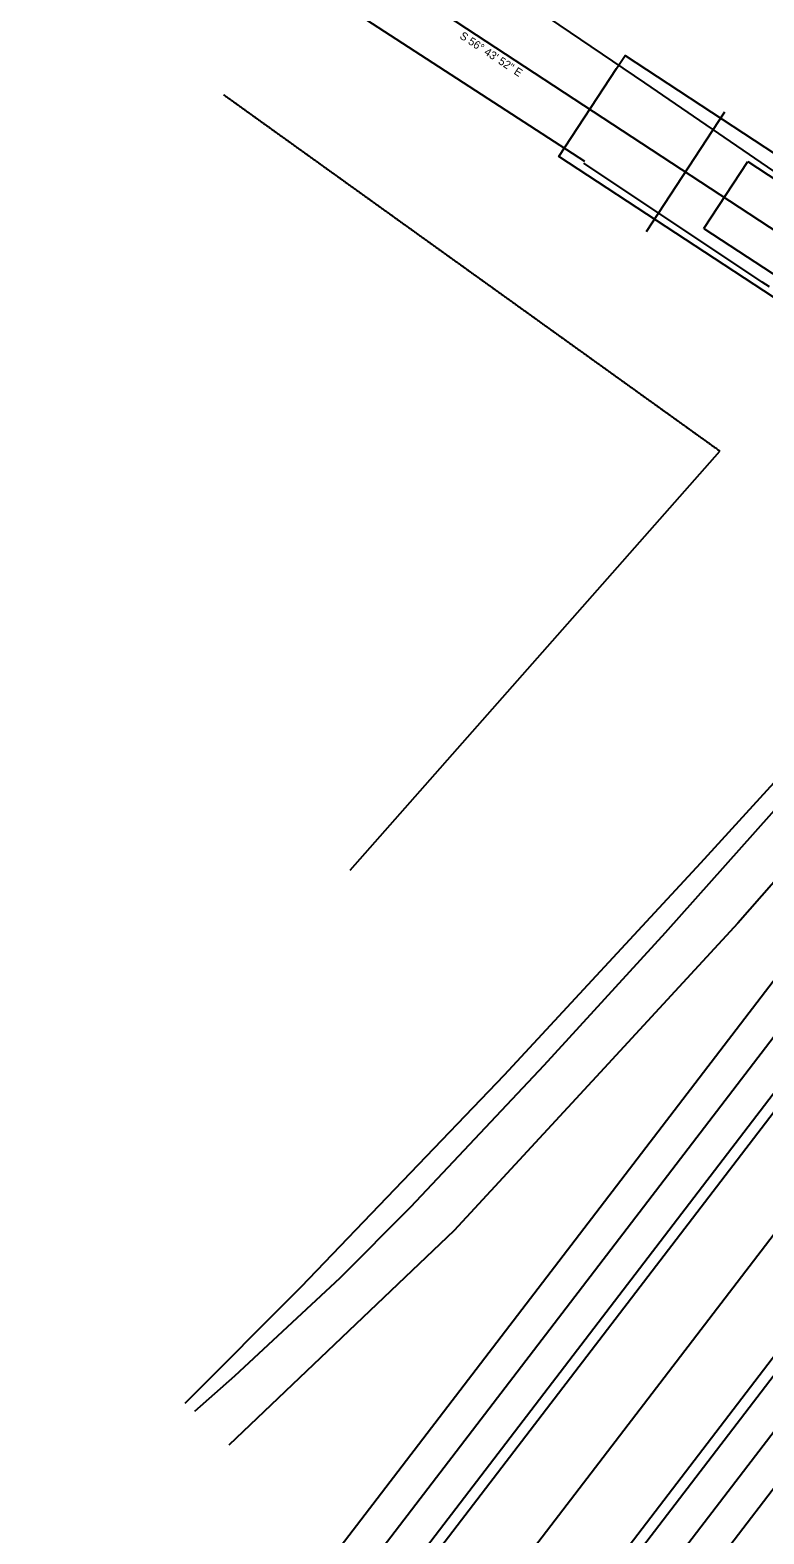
# Model space of a CAD drawing. Extents: x 1811884 to 1864767, y 229883 to 701064.
# Drawn here: x 1857252 to 1857509, y 693923 to 694449 of the extents above; entities that cross this region are included whole.
import ezdxf

# ---------------------------------------------------------------- set-up
doc = ezdxf.new("R2010")
doc.units = 0
for name, color, linetype in [('GE_X_CL_20', 7, 'Continuous'), ('GK_Patterns', 7, 'Continuous'), ('PM_X_Dotted_Line', 7, 'Continuous'), ('PV_P_EOP', 7, 'Continuous'), ('PV_X_EOP', 7, 'Continuous'), ('PV_X_Shoulder', 7, 'Continuous'), ('RD_P_GR_Lt', 7, 'Continuous'), ('RD_P_GR_Rt', 7, 'Continuous'), ('RD_X_GR_Lt', 7, 'Continuous'), ('RD_X_GR_Rt', 7, 'Continuous'), ('RW_P_Const_Limits', 7, 'Continuous'), ('RW_X_Esmt_LA', 7, 'Continuous'), ('RW_X_Fee_RW', 7, 'Continuous'), ('SC_Scratch1', 7, 'Continuous')]:
    doc.layers.add(name, color=color, linetype=linetype)

msp = doc.modelspace()

# ---------------------------------------------------------------- linework, layer by layer
at = {"layer": 'GE_X_CL_20'}
for p, q in [((1856038.27, 695346.31), (1858797.33, 693536.09)), ((1849938.53, 684134.24), (1857781.86, 694380.23))]:
    msp.add_line(p, q, dxfattribs=at)
at = {"layer": 'GK_Patterns'}
msp.add_line((1857495, 694420.44), (1857467.58, 694378.64), dxfattribs=at)
at = {"layer": 'PM_X_Dotted_Line'}
for p, q in [((1849895.65, 684167.07), (1857634.93, 694277.14)), ((1849905.18, 684159.77), (1857644.6, 694270.02)), ((1849971.88, 684108.72), (1857715.1, 694223.93))]:
    msp.add_line(p, q, dxfattribs=at)
msp.add_lwpolyline([(1857597.14, 694247.78), (1857499.66, 694136.79), (1857452.86, 694086.05), (1857400.42, 694029.19), (1857321.55, 693954.09)], dxfattribs=at)
at = {"layer": 'PV_P_EOP'}
for p, q in [((1857487.73, 694379.77), (1857503.09, 694403.18)), ((1857503.09, 694403.18), (1857550.9, 694371.81)), ((1857487.73, 694379.77), (1857533.83, 694349.52))]:
    msp.add_line(p, q, dxfattribs=at)
at = {"layer": 'PV_X_EOP'}
for p, q in [((1849917.89, 684150.05), (1857657.99, 694261.19)), ((1849959.18, 684118.44), (1857701.58, 694232.59))]:
    msp.add_line(p, q, dxfattribs=at)
msp.add_lwpolyline([(1857606.72, 694294.54), (1857568.77, 694249.34), (1857528.08, 694203.18), (1857486.54, 694157.74), (1857417.89, 694083.55), (1857346.7, 694009.38), (1857306.23, 693968.66)], dxfattribs=at)
at = {"layer": 'PV_X_Shoulder'}
for p, q in [((1849914.71, 684152.48), (1857654.31, 694262.96)), ((1849962.35, 684116.01), (1857705.14, 694230.65)), ((1849981.41, 684101.42), (1857725.06, 694217.19))]:
    msp.add_line(p, q, dxfattribs=at)
msp.add_lwpolyline([(1857611.94, 694290.62), (1857587.74, 694262.22), (1857555.83, 694224.77), (1857516.23, 694180.44), (1857474.18, 694133.37), (1857431.78, 694086.9), (1857385.17, 694037.4), (1857360.36, 694012.59), (1857323.57, 693978.21), (1857309.55, 693965.85)], dxfattribs=at)
at = {"layer": 'RD_P_GR_Lt'}
msp.add_line((1857508.16, 694361.03), (1857445.75, 694402.62), dxfattribs=at)
at = {"layer": 'RD_P_GR_Rt'}
msp.add_line((1857528.96, 694388.35), (1857467.05, 694430.68), dxfattribs=at)
at = {"layer": 'RD_X_GR_Lt'}
msp.add_line((1857446.11, 694403.17), (1857367.47, 694454.21), dxfattribs=at)
at = {"layer": 'RD_X_GR_Rt'}
msp.add_line((1857467.05, 694430.68), (1857374.01, 694493.93), dxfattribs=at)
at = {"layer": 'RW_P_Const_Limits'}
msp.add_lwpolyline([(1857457.17, 694435.7), (1857460.19, 694440.29), (1857550.46, 694381.06), (1857566.92, 694374.74), (1857583.72, 694363.9), (1857585.98, 694354.91), (1857812.54, 694207.41), (1857831.82, 694200.62), (1857860.09, 694181.63), (1857883.95, 694161.73), (1857938.72, 694129.31), (1857939.81, 694128.59), (1857935.42, 694121.92), (1857912.81, 694087.45), (1857834.01, 694143.46), (1857818.03, 694145.83), (1857799.92, 694157.36), (1857791.32, 694171.29), (1857565.48, 694319.69), (1857549.3, 694322.83), (1857529.11, 694336.08), (1857518.94, 694351.25), (1857437.03, 694404.99)], close=True, dxfattribs=at)
at = {"layer": 'RW_X_Esmt_LA'}
msp.add_line((1857364.06, 694155.25), (1857493.37, 694301.92), dxfattribs=at)
at = {"layer": 'RW_X_Fee_RW'}
for points in [[(1857319.67, 694426.64), (1857320.45, 694426.08), (1857321.23, 694425.52), (1857322.02, 694424.96), (1857322.8, 694424.4), (1857323.58, 694423.84), (1857324.36, 694423.27), (1857325.15, 694422.71), (1857325.93, 694422.15), (1857326.71, 694421.59), (1857327.49, 694421.03), (1857328.28, 694420.46), (1857329.06, 694419.9), (1857329.84, 694419.34), (1857330.62, 694418.78), (1857331.41, 694418.22), (1857332.19, 694417.65), (1857332.97, 694417.09), (1857333.75, 694416.53), (1857334.53, 694415.97), (1857335.32, 694415.41), (1857336.1, 694414.85), (1857336.88, 694414.28), (1857337.66, 694413.72), (1857338.45, 694413.16), (1857339.23, 694412.6), (1857340.01, 694412.04), (1857340.79, 694411.47), (1857341.58, 694410.91), (1857342.36, 694410.35), (1857343.14, 694409.79), (1857343.92, 694409.23), (1857344.71, 694408.67), (1857345.49, 694408.1), (1857346.27, 694407.54), (1857347.05, 694406.98), (1857347.84, 694406.42), (1857348.62, 694405.86), (1857349.4, 694405.29), (1857350.18, 694404.73), (1857350.97, 694404.17), (1857351.75, 694403.61), (1857352.53, 694403.05), (1857353.31, 694402.49), (1857354.1, 694401.92), (1857354.88, 694401.36), (1857355.66, 694400.8), (1857356.44, 694400.24), (1857357.23, 694399.68), (1857358.01, 694399.11), (1857358.79, 694398.55), (1857359.57, 694397.99), (1857360.35, 694397.43), (1857361.14, 694396.87), (1857361.92, 694396.31), (1857362.7, 694395.74), (1857363.48, 694395.18), (1857364.27, 694394.62), (1857365.05, 694394.06), (1857365.83, 694393.5), (1857366.61, 694392.93), (1857367.4, 694392.37), (1857368.18, 694391.81), (1857368.96, 694391.25), (1857369.74, 694390.69), (1857370.53, 694390.13), (1857371.31, 694389.56), (1857372.09, 694389), (1857372.87, 694388.44), (1857373.66, 694387.88), (1857374.44, 694387.32), (1857375.22, 694386.75), (1857376, 694386.19), (1857376.79, 694385.63), (1857377.57, 694385.07)], [(1857377.57, 694385.07), (1857378.35, 694384.51), (1857379.13, 694383.94), (1857379.92, 694383.38), (1857380.7, 694382.82), (1857381.48, 694382.26), (1857382.26, 694381.7), (1857383.04, 694381.14), (1857383.83, 694380.57), (1857384.61, 694380.01), (1857385.39, 694379.45), (1857386.17, 694378.89), (1857386.96, 694378.33), (1857387.74, 694377.76), (1857388.52, 694377.2), (1857389.3, 694376.64), (1857390.09, 694376.08), (1857390.87, 694375.52), (1857391.65, 694374.96), (1857392.43, 694374.39), (1857393.22, 694373.83), (1857394, 694373.27), (1857394.78, 694372.71), (1857395.56, 694372.15), (1857396.35, 694371.58), (1857397.13, 694371.02), (1857397.91, 694370.46), (1857398.69, 694369.9), (1857399.48, 694369.34), (1857400.26, 694368.78), (1857401.04, 694368.21), (1857401.82, 694367.65), (1857402.61, 694367.09), (1857403.39, 694366.53), (1857404.17, 694365.97), (1857404.95, 694365.4), (1857405.73, 694364.84), (1857406.52, 694364.28), (1857407.3, 694363.72), (1857408.08, 694363.16), (1857408.86, 694362.6), (1857409.65, 694362.03), (1857410.43, 694361.47), (1857411.21, 694360.91), (1857411.99, 694360.35), (1857412.78, 694359.79), (1857413.56, 694359.22), (1857414.34, 694358.66), (1857415.12, 694358.1), (1857415.91, 694357.54), (1857416.69, 694356.98), (1857417.47, 694356.41), (1857418.25, 694355.85), (1857419.04, 694355.29), (1857419.82, 694354.73), (1857420.6, 694354.17), (1857421.38, 694353.61), (1857422.17, 694353.04), (1857422.95, 694352.48), (1857423.73, 694351.92), (1857424.51, 694351.36), (1857425.3, 694350.8), (1857426.08, 694350.23), (1857426.86, 694349.67), (1857427.64, 694349.11), (1857428.42, 694348.55), (1857429.21, 694347.99), (1857429.99, 694347.43), (1857430.77, 694346.86), (1857431.55, 694346.3), (1857432.34, 694345.74), (1857433.12, 694345.18), (1857433.9, 694344.62), (1857434.68, 694344.05), (1857435.47, 694343.49)], [(1857435.47, 694343.49), (1857436.25, 694342.93), (1857437.03, 694342.37), (1857437.81, 694341.81), (1857438.6, 694341.25), (1857439.38, 694340.68), (1857440.16, 694340.12), (1857440.94, 694339.56), (1857441.73, 694339), (1857442.51, 694338.44), (1857443.29, 694337.87), (1857444.07, 694337.31), (1857444.86, 694336.75), (1857445.64, 694336.19), (1857446.42, 694335.63), (1857447.2, 694335.07), (1857447.99, 694334.5), (1857448.77, 694333.94), (1857449.55, 694333.38), (1857450.33, 694332.82), (1857451.12, 694332.26), (1857451.9, 694331.69), (1857452.68, 694331.13), (1857453.46, 694330.57), (1857454.24, 694330.01), (1857455.03, 694329.45), (1857455.81, 694328.89), (1857456.59, 694328.32), (1857457.37, 694327.76), (1857458.16, 694327.2), (1857458.94, 694326.64), (1857459.72, 694326.08), (1857460.5, 694325.51), (1857461.29, 694324.95), (1857462.07, 694324.39), (1857462.85, 694323.83), (1857463.63, 694323.27), (1857464.42, 694322.7), (1857465.2, 694322.14), (1857465.98, 694321.58), (1857466.76, 694321.02), (1857467.55, 694320.46), (1857468.33, 694319.9), (1857469.11, 694319.33), (1857469.89, 694318.77), (1857470.68, 694318.21), (1857471.46, 694317.65), (1857472.24, 694317.09), (1857473.02, 694316.52), (1857473.81, 694315.96), (1857474.59, 694315.4), (1857475.37, 694314.84), (1857476.15, 694314.28), (1857476.93, 694313.72), (1857477.72, 694313.15), (1857478.5, 694312.59), (1857479.28, 694312.03), (1857480.06, 694311.47), (1857480.85, 694310.91), (1857481.63, 694310.34), (1857482.41, 694309.78), (1857483.19, 694309.22), (1857483.98, 694308.66), (1857484.76, 694308.1), (1857485.54, 694307.54), (1857486.32, 694306.97), (1857487.11, 694306.41), (1857487.89, 694305.85), (1857488.67, 694305.29), (1857489.45, 694304.73), (1857490.24, 694304.16), (1857491.02, 694303.6), (1857491.8, 694303.04), (1857493.37, 694301.92)]]:
    msp.add_spline(points, degree=3, dxfattribs=at)
at = {"layer": 'SC_Scratch1'}
msp.add_line((1857510.77, 694359.32), (1857508.15, 694361.04), dxfattribs=at)

# ---------------------------------------------------------------- texts
at = {"layer": 'GE_X_CL_20'}
msp.add_text('S 56%%d 43\' 52" E', height=2.8, rotation=326.731, dxfattribs=at).set_placement((1857402.06, 694446.5))

doc.saveas('drawing.dxf')
